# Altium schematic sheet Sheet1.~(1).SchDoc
size A; SheetNumber: 1; SheetTotal: 1
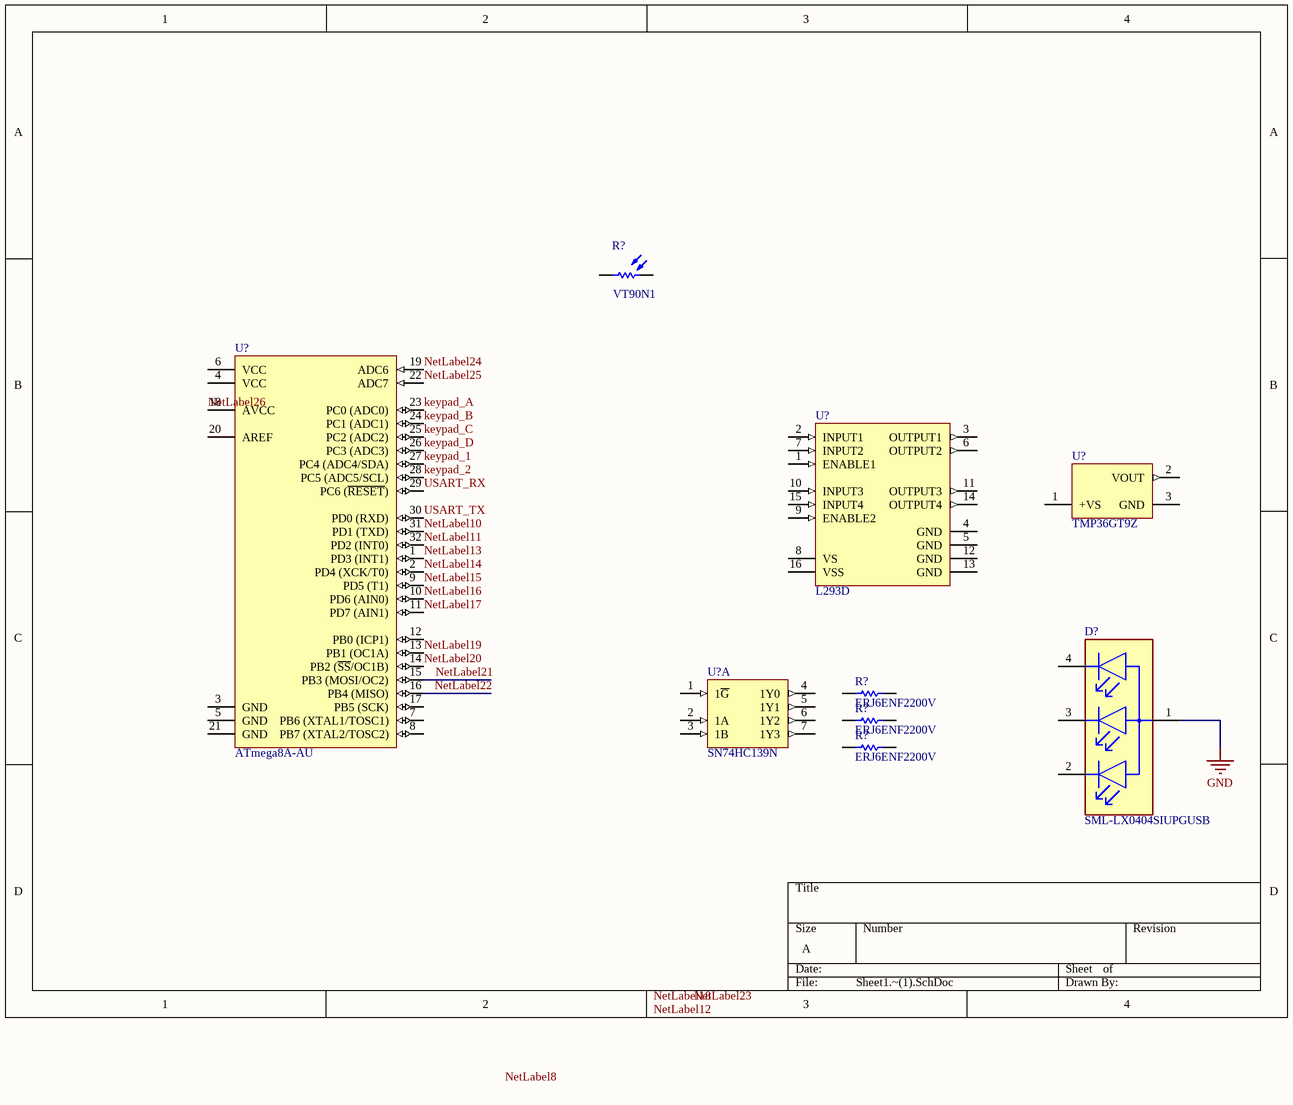
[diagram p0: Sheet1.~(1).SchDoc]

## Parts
(Parts that share a designator on the sheet are numbered #1, #2 ... from top to bottom, then left to right.)
D?  SML-LX0404SIUPGUSB  [FP-SML-LX0404SIUPGUSB-MFG]
R?#1  VT90N1  [EXCE-VT90N1]
R?#2  ERJ6ENF2200V  [RESC2013X70X40NL20T20]
R?#3  ERJ6ENF2200V  [RESC2013X70X40NL20T20]
R?#4  ERJ6ENF2200V  [RESC2013X70X40NL20T20]
U?#1  ATmega8A-AU  [32A_N]
U?#2  L293D  [STM-L293D-16]
U?#3  TMP36GT9Z  [ADI-T-3]
U?#4  SN74HC139N  [N0016A]  (part A of 3)

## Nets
GND: D?.1(Common_Anode)
keypad_1: U?#1.27(PC4_(ADC4/SDA))
keypad_2: U?#1.28(PC5_(ADC5/SCL))
keypad_A: U?#1.23(PC0_(ADC0))
keypad_B: U?#1.24(PC1_(ADC1))
keypad_C: U?#1.25(PC2_(ADC2))
keypad_D: U?#1.26(PC3_(ADC3))
NetLabel10: U?#1.31(PD1_(TXD))
NetLabel11: U?#1.32(PD2_(INT0))
NetLabel13: U?#1.1(PD3_(INT1))
NetLabel14: U?#1.2(PD4_(XCK/T0))
NetLabel15: U?#1.9(PD5_(T1))
NetLabel16: U?#1.10(PD6_(AIN0))
NetLabel17: U?#1.11(PD7_(AIN1))
NetLabel19: U?#1.13(PB1_(OC1A))
NetLabel20: U?#1.14(PB2_(~{SS}/OC1B))
NetLabel21: U?#1.15(PB3_(MOSI/OC2))
NetLabel22: U?#1.16(PB4_(MISO))
NetLabel24: U?#1.19(ADC6)
NetLabel25: U?#1.22(ADC7)
NetLabel26: U?#1.18(AVCC)
USART_RX: U?#1.29(PC6_(~{RESET}))
USART_TX: U?#1.30(PD0_(RXD))

Not connected (* = marked no-connect by the designer): D? 2(Red_C) 3(Blue_C) 4(Green_C); R?#1 1 2; R?#2 1 2; R?#3 1 2; R?#4 1 2; U?#1 3(GND) 4(VCC) 5(GND) 6(VCC) 7(PB6_(XTAL1/TOSC1)) 8(PB7_(XTAL2/TOSC2)) 12(PB0_(ICP1)) 17(PB5_(SCK)) 20(AREF) 21(GND); U?#2 1(ENABLE1) 2(INPUT1) 3(OUTPUT1) 4(GND) 5(GND) 6(OUTPUT2) 7(INPUT2) 8(VS) 9(ENABLE2) 10(INPUT3) 11(OUTPUT3) 12(GND) 13(GND) 14(OUTPUT4) 15(INPUT4) 16(VSS); U?#3 1(+VS) 2(VOUT) 3(GND); U?#4 1(1~{G}) 2(1A) 3(1B) 4(1Y0) 5(1Y1) 6(1Y2) 7(1Y3)

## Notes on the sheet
- Labels drawn without touching a wire or pin: NetLabel8, NetLabel12, NetLabel18, NetLabel23

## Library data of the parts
D? = CMP-2000-07119-2: LED RGB CLEAR SMD; Test Current: 2mA; Wavelength: 465nm; Color: Blue; Lens Style: Square; Power Rating: 30mW; Lens Color: Colorless; Number of LEDs: 3; Viewing Angle: 120°; Luminous Intensity: 20mcd; Forward Voltage: 2.73V
R?#1 = CMP-2000-07406-1: Photoconductive Resistor, 200 kOhm, 100 V, 80 mW, -40 to 75 degC, 2-Pin THD, RoHS; Manufacturer: Excelitas Technology; SVHC: Cadmiumchloride(15-Jun-2015); Power Rating: 80mW; Resistance @ Lux: 12kohm; Voltage Rating: 100V
R?#2-R?#4 = CMP-2001-00044-1: Manufacturer: Panasonic
U?#1 = CMP-0095-00219-2: 8-bit AVR Microcontroller, 2.7-5.5V, 16MHz, 8KB Flash, 512 Bytes EEPROM, 1KB SRAM, 32-pin TQFP, Industrial Grade (-40°C to 85°C)
U?#2 = CMP-2000-06524-1: Push-Pull Four Channel Driver with Diode, 4.5 to 36 V, -40 to 150 degC, 16-Pin PDIP, RoHS, Tube; Manufacturer: STMicroelectronics; Number of Outputs: 4; Current - Peak Output: 1.2A; Current - Output / Channel: 600mA; Input Type: Non-Inverting; Other Related Documents: L293DViewAllSpecifications; Dynamic Catalog: HalfBridge; Voltage - Supply: 4.5V~36V; Other Names: 497-2936-5
U?#3 = CMP-0887-00067-1: Low Voltage Temperature Sensor, 2.7 to 5.5 V Supply, Industrial, 3-pin TO92 (T-3), Tray; Manufacturer: Analog Devices
U?#4 = CMP-1633-00660-2: Dual 2-Line To 4-Line Decoders/Demultiplexers, N0016A, TUBE; Manufacturer: Texas Instruments; Technology Family: HC; VCC(Min)(V): 2; Voltage(Nom)(V): 3.3,5; F @ Nom Voltage(Max)(Mhz): 28; Output Type: CMOS; Bits(#): 4; VCC(Max)(V): 6; ICC @ Nom Voltage(Max)(mA): 0.08; Function: Decoder/Demultiplexer; Input Type: LVTTL/CMOS; Output Drive (IOL/IOH)(Max)(mA): 5.2/-5.2; Schmitt Trigger: No; Rating: Catalog; Configuration: 2：4; tpd @ Nom Voltage(Max)(ns): 44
